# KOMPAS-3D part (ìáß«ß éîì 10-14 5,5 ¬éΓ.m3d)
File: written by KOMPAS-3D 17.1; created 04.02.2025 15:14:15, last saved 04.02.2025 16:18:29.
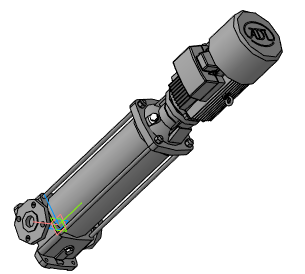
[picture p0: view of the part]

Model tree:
1. Операция без истории:2  (labels: Насос ВМН 10-14 5,5 кВт)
